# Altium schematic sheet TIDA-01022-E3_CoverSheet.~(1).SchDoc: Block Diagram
size 431 x 279 mm; Date: Not shown in title block; ApprovedBy: Not shown in title block; CheckedBy: Not shown in title block; Author: Not shown in title block; CompanyName: Not shown in title block; DrawnBy: Avinash N; Engineer: Not shown in title block; Organization: Not shown in title block; Address1: Not shown in title block; Address2: Not shown in title block; Address3: Not shown in title block; Address4: Not shown in title block; DocumentNumber: 1; Revision: Use project parameter SCH_Rev; SheetNumber: 1; SheetTotal: 26; PageSetup: Record=PageOptions¦CenterHorizontal=True¦CenterVertical=True¦PrintScale=1.00¦XCorrection=1.00¦YCorrection=1.00¦PrintKind=0¦BorderSize=5000000¦LeftOffset=0¦BottomOffset=0¦Orientation=2¦PaperLength=1000¦PaperWidth=1000¦Scale=100¦PaperSource=15¦PrintQuality=600¦MediaType=1¦DitherType=10¦PaperKind=Letter¦PrintScaleMode=1
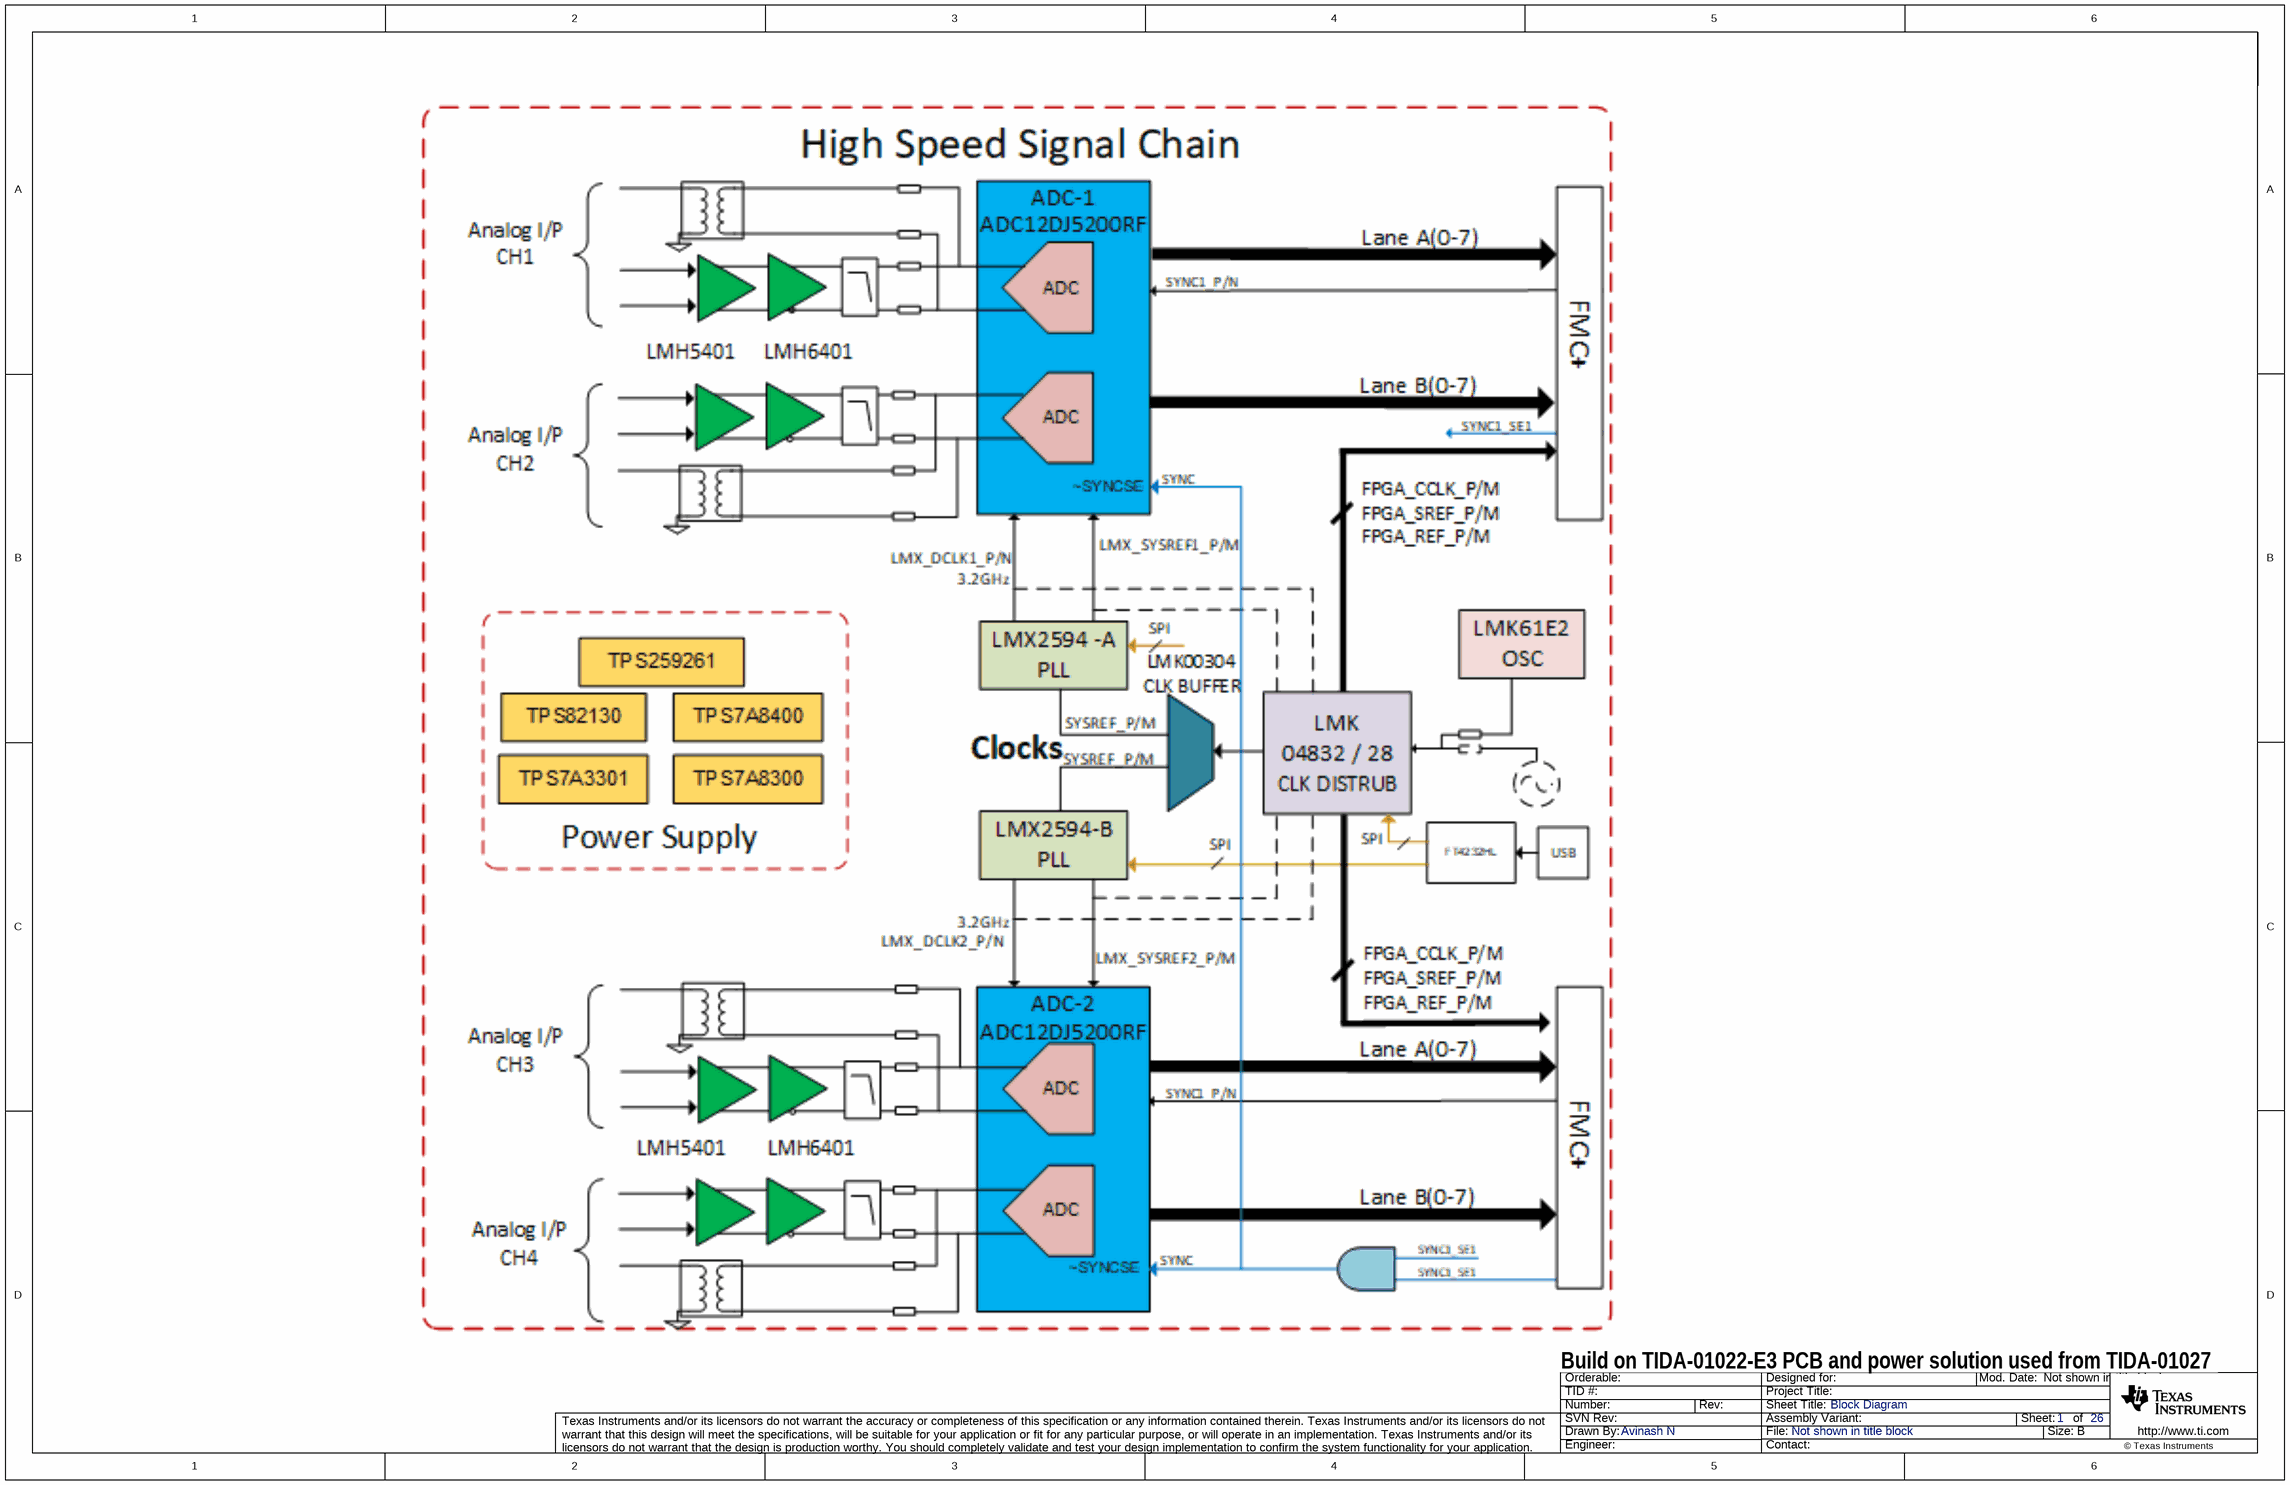
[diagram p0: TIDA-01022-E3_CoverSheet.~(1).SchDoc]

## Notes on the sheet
- Build on TIDA-01022-E3 PCB and power solution used from TIDA-01027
